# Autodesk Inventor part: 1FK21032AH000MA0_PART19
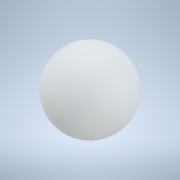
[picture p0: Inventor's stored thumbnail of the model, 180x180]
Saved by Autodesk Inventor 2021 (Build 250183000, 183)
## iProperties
Created: 2025-04
Part Number: 1FK21032AH000MA0_PART19
Material: Generic
Catalog Web Link: www.3dfindit.com
Description: -Servo synchronous motor
Document SubType Name: Modeling
Designer: psAdmin
Mass: 0.113097 g
Surface Area: 1.13097 cm^2
Volume: 0.113097 cm^3
Density: 1 g/cm^3
Appearance: PSOLRGB-212-217-219
Category: PARTsolutions
Title: 1FK21032AH000MA0_PART19
Author: Cadenas PARTsolutions
Comments: Servo synchronous motor
Sending System: PARTsolutions
Preprocessor: ST-DEVELOPER v19.3
PSOL_IDENT_0: {$CADENAS_DATA/23d-libs/siemens_ag/_cat_/45/10/1fk21032ah000ma0.prj},216 {VTYP=3D},{NB=1FK21032AH000
PSOL_IDENT_1: MA0_PART19},{LINA=1FK21032AH000MA0_PART19},{NN=1FK21032AH000MA0_PART19},{NOPRJ=TRUE},{DATE=19.08.202
PSOL_IDENT_2: 5 14:00:35},{GEOMDATE=30.07.2025 02:02:03},{VERSION=},{LINEID=10},{WBVAR=},{WBNUMERIC=}  {NB=1FK2103
PSOL_IDENT_3: 2AH000MA0_PART19},{LINA=1FK21032AH000MA0_PART19},{KT=DUMMY},{PREVIEW=../../../_pool_/14/8e/p_d211_xx
PSOL_IDENT_4: _00426j.png},{DESCSHORT=SIMOTICS S-1FK2 HD, SINAMICS S210 3AC 400V-480V, 0.59 Nm, 4500 rpm},{DESCLON
PSOL_IDENT_5: G=SIMOTICS S-1FK2 HD servo motor M0=0.64 Nm; PN = 0.28 kW at nN=4500 rpm (380-480 V); PN = 0.167 kW
PSOL_IDENT_6: at nN=2500 rpm (200-240 V); degree of protection IP64; cylindrical shaft D14 x 30 mm; absolute encod
PSOL_IDENT_7: er 22-bit + 12-bit multiturn (encoder AM22DQC); with OCC interface; plug size M17, rotatable; SIMOTI
PSOL_IDENT_8: CS S-1FK2 servomotorfor a wide range of uses in industrial environments. SIMOTICS S‑1FK2 servomotors
PSOL_IDENT_9: are compact synchronous motors with a high dynamic performance that set themselves apart as a resul
PSOL_IDENT_10: t of their high power density, degree of protection and overload capability. The motors are availabl
PSOL_IDENT_11: e in two variants: as High Dynamic variant (highest dynamic performance as a result of the low intri
PSOL_IDENT_12: nsic moment of inertia for applications demanding a high dynamic performance with low moved masses)
PSOL_IDENT_13: - and as Compact variant (precise and stable closed-loop control for medium up to large moved masses
PSOL_IDENT_14: as a result of a medium intrinsic moment of inertia). SIMOTICSS‑1FK2 servomotors fully exploit thei
PSOL_IDENT_15: r strengths in a system with the SINAMICSS210 frequency converter and simple connection using the on
PSOL_IDENT_16: e cable connection (OCC). Advantages include the short control and positioning times, fast and preci
PSOL_IDENT_17: se correction of disturbing quantities as well as stable control with a high dynamic performance. Th
PSOL_IDENT_18: e servo motors can be configured to address a wide range of requirements. For example with and witho
PSOL_IDENT_19: ut holding brake, IP64 or IP65 degree of protection, singleturn or multiturn absolute encoders - to
PSOL_IDENT_20: name just a few. Further, the servomotors are available in different shaft heights extending from 20
PSOL_IDENT_21: to 100. A shaft sealing ring is available to achieve an IP65 degree of protection and for subsequen
PSOL_IDENT_22: t mounting at the motor or as spare part. SIMOTICS - the optimum motor for each and every motion con
PSOL_IDENT_23: trol application.},{INTNO=195125335004},{SUPPLIERALTNO=1FK2103-2AH00-0MA0},{MANUID=1FK21032AH000MA0}
PSOL_IDENT_24: ,{MANUNAME=Siemens},{MANUTYPEDESC=SYNCHRONOUS MOTOR 1FK2 HD 0,64 NM},{AAU732=SIMOTICS},{AAO057=S-1FK
PSOL_IDENT_25: 2},{AAU734=SIMOTICS S-1FK2 HD servo motor M0=0.64 Nm; PN = 0.28 kW at nN=4500 rpm (380-480 V); PN =
PSOL_IDENT_26: 0.167 kW at nN=2500 rpm (200-240 V); degree of protection IP64; cylindrical shaft D14 x 30 mm; absol
PSOL_IDENT_27: ute encoder 22-bit + 12-bit multiturn (encoder AM22DQC); with OCC interface; plug size M17, rotatabl
PSOL_IDENT_28: e;},{AAW338=SYNCHRONOUS MOTOR 1FK2 HD 0,64 NM},{AAO742=SIMOTICS},{AAO663=4034106444624},{NOCUPEROU=1
PSOL_IDENT_29: },{PRICEQUANTITY=1},{QUANTITYMIN=1},{QUANTITYINT=1},{CTN=85015100},{COO=RO},{AAO676=1FK2103-2AH00-0M
PSOL_IDENT_30: A0},{AAO677=Siemens AG},{ORDERUNIT=C62},{CONTENTUNIT=C62}
NB: 1FK21032AH000MA0_PART19
NT: Servo synchronous motor
NBSYN: $MANUID._PART19
LINA: 1FK21032AH000MA0_PART19
CATALOG: SIEMENS
PREVIEW: ../../../_pool_/14/8e/p_d211_xx_00426j.png
DESCSHORT: SIMOTICS S-1FK2 HD, SINAMICS S210 3AC 400V-480V, 0.59 Nm, 4500 rpm
DESCLONG: SIMOTICS S-1FK2 HD servo motor M0=0.64 Nm; PN = 0.28 kW at nN=4500 rpm (380-480 V); PN = 0.167 kW at nN=2500 rpm (200-240 V); degree of protection IP64; cylindr
INTNO: 195125335004
SUPPLIERALTNO: 1FK2103-2AH00-0MA0
MANUID: 1FK21032AH000MA0
MANUNAME: Siemens
MANUTYPEDESC: SYNCHRONOUS MOTOR 1FK2 HD 0,64 NM
AAU732: SIMOTICS
AAO057: S-1FK2
AAU734: SIMOTICS S-1FK2 HD servo motor M0=0.64 Nm; PN = 0.28 kW at nN=4500 rpm (380-480 V); PN = 0.167 kW at nN=2500 rpm (200-240 V); degree of protection IP64; cylindr
AAW338: SYNCHRONOUS MOTOR 1FK2 HD 0,64 NM
AAO742: SIMOTICS
AAO663: 4034106444624.0
NOCUPEROU: 1
PRICEQUANTITY: 1
QUANTITYMIN: 1
QUANTITYINT: 1
CTN: 85015100
COO: RO
ARTICLENO: 1FK21032AH000MA0_PART19
BOMINFO: 1FK21032AH000MA0_PART19
CREATOR: CADENAS GmbH
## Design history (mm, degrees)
feature "2025_04_17_15_00_20_0760"
body "Solid1"
